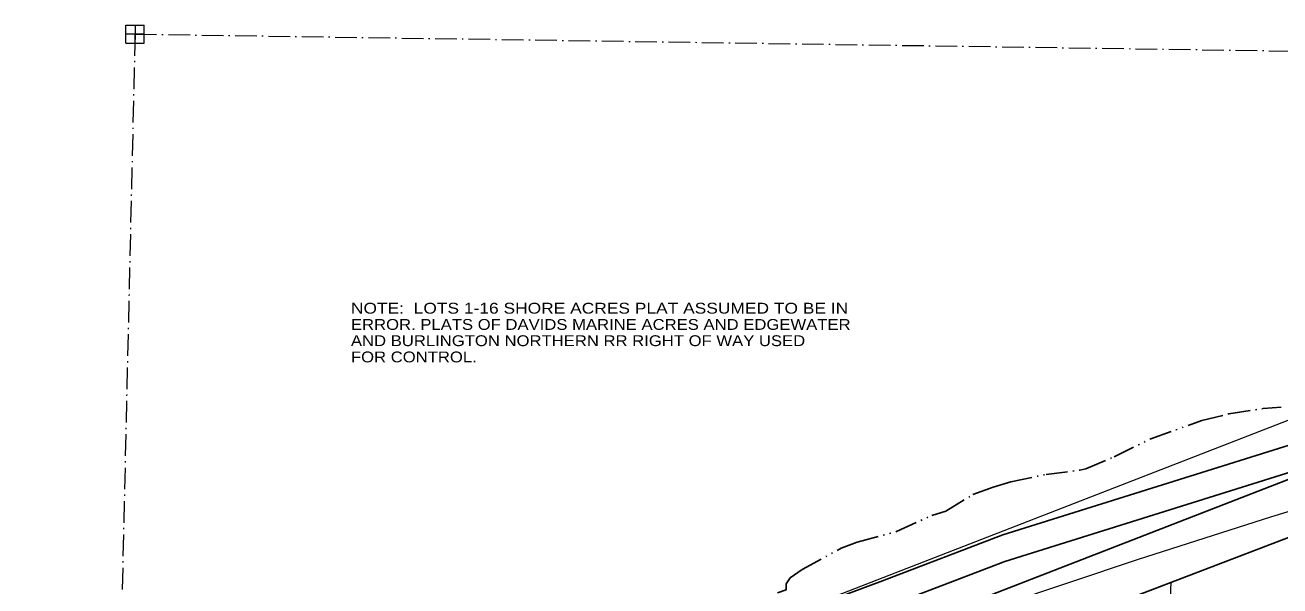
# Model space of a CAD drawing. Extents: x -861682 to -858969, y -1797841 to -1795153.
# Drawn here: x -861677 to -860981, y -1795463 to -1795153 of the extents above; entities that cross this region are included whole.
import ezdxf

# ---------------------------------------------------------------- set-up
doc = ezdxf.new("R2010")
doc.units = 0
doc.header["$LTSCALE"] = 2.4
doc.linetypes.add('DASH_DOUBLE_DOT', pattern=[9.2, 5, -1.2, 0.3, -1.2, 0.3, -1.2])
doc.linetypes.add('DOT_DASHED', pattern=[7.7, 5, -1.2, 0.3, -1.2])
for name, color, linetype, lineweight in [('16', 7, 'DASH_DOUBLE_DOT', 25), ('18', 7, 'Continuous', 13), ('30', 7, 'Continuous', 13), ('42', 7, 'Continuous', 25), ('46', 7, 'Continuous', 13), ('6', 7, 'Continuous', 25), ('61', 7, 'Continuous', 13)]:
    doc.layers.add(name, color=color, linetype=linetype, lineweight=lineweight)

msp = doc.modelspace()

# ---------------------------------------------------------------- linework, layer by layer
at = {"layer": '16'}
msp.add_lwpolyline([(-861626.723, -1795630.941), (-861472.61, -1795555.55), (-861383.169, -1795515.308), (-861255.062, -1795465.277), (-861255.091, -1795461.969), (-861252.757, -1795458.64), (-861246.18, -1795454.093), (-861224.544, -1795442.326), (-861215.594, -1795438.939), (-861193.906, -1795433.079), (-861174.372, -1795424.165), (-861166.595, -1795421.734), (-861151.552, -1795412.624), (-861140.246, -1795408.508), (-861130.583, -1795405.588), (-861111.007, -1795401.4), (-861092.36, -1795399.11), (-861089.058, -1795398.373), (-861073.286, -1795391.618), (-861053.05, -1795381.754), (-861024.784, -1795371.582), (-861009.693, -1795367.906), (-860990.816, -1795364.905), (-860980.662, -1795364.108)], dxfattribs=at)
at = {"layer": '18'}
msp.add_lwpolyline([(-861627.784, -1795676.931), (-861596.674, -1795662.729), (-861531.982, -1795629.555), (-861487.69, -1795614.518), (-861432.082, -1795596.546), (-861364.083, -1795563.344), (-861330.912, -1795546.255), (-861278.234, -1795519.917), (-861241.977, -1795502.494), (-861200.029, -1795489.604), (-861135.894, -1795473.921), (-861059.793, -1795448.445), (-860986.512, -1795424.884), (-860905.443, -1795400.073), (-860827.906, -1795376.712), (-860758.776, -1795364.765), (-860677.115, -1795353.655), (-860512.688, -1795322.681), (-860272.176, -1795291.516), (-860031.805, -1795256.984)], dxfattribs=at)
at = {"layer": '30'}
msp.add_line((-861054.629, -1795762.201), (-861041.637, -1795461.116), dxfattribs=at)
msp.add_lwpolyline([(-861626.562, -1795623.983), (-861624.447, -1795622.863), (-860925.467, -1795351.444)], dxfattribs=at)
at = {"layer": '42'}
msp.add_line((-861114.992, -1795489.15), (-860970.492, -1795433.926), dxfattribs=at)
msp.add_lwpolyline([(-861627.374, -1795659.18), (-861609.983, -1795649.976), (-860911.743, -1795378.903)], dxfattribs=at)
at = {"layer": '6'}
for points in [[(-861626.979, -1795642.068), (-861544.533, -1795599.421), (-861437.181, -1795553.823), (-861360.226, -1795517.943), (-861269.063, -1795485.483), (-861201.703, -1795460.32), (-861135.053, -1795434.926), (-860930.273, -1795370.755), (-860759.796, -1795329.096), (-860655.328, -1795305.026), (-860586.415, -1795295.208), (-860452.636, -1795272.3), (-860334.137, -1795258.505), (-859981.661, -1795225.976)], [(-861627.338, -1795657.588), (-861543.402, -1795614.17), (-861436.05, -1795568.572), (-861359.095, -1795532.692), (-861267.932, -1795500.232), (-861200.572, -1795475.069), (-861133.922, -1795449.675), (-860929.142, -1795385.504), (-860758.665, -1795343.845), (-860654.197, -1795319.775), (-860585.284, -1795309.957), (-860451.505, -1795287.049), (-860333.006, -1795273.254), (-859980.53, -1795240.725)]]:
    msp.add_lwpolyline(points, dxfattribs=at)
at = {"layer": '61'}
for p, q in [((-861620.801, -1795152.51), (-861610.801, -1795152.51)), ((-861620.801, -1795162.51), (-861620.801, -1795152.51)), ((-861615.801, -1795152.51), (-861615.801, -1795157.51)), ((-861610.801, -1795162.51), (-861610.801, -1795152.51)), ((-861610.801, -1795157.51), (-861620.801, -1795157.51)), ((-861615.801, -1795162.51), (-861615.801, -1795157.51)), ((-861620.801, -1795162.51), (-861610.801, -1795162.51))]:
    msp.add_line(p, q, dxfattribs=at)
at = {"layer": '61', "linetype": 'DOT_DASHED'}
for q in [(-861676.699, -1797797.295), (-858974.429, -1795196.105)]:
    msp.add_line((-861615.801, -1795157.51), q, dxfattribs=at)

# ---------------------------------------------------------------- texts
at = {"layer": '46'}
for s, width, p in [('NOTE:  LOTS 1-16 SHORE ACRES PLAT ASSUMED TO BE IN', 1.2, (-861496.166, -1795312.347)), ('ERROR. PLATS OF DAVIDS MARINE ACRES AND EDGEWATER', 1.15, (-861496.166, -1795321.347)), ('AND BURLINGTON NORTHERN RR RIGHT OF WAY USED', 1.15, (-861496.166, -1795330.347)), ('FOR CONTROL.', 1.15, (-861496.166, -1795339.347))]:
    msp.add_text(s, height=6, dxfattribs=dict(at, width=width)).set_placement(p)

doc.saveas('drawing.dxf')
